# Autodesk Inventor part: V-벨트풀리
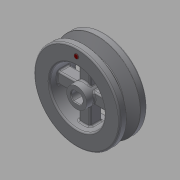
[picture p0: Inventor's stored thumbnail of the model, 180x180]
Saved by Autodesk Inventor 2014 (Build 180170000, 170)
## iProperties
Created: 2018-01
Part Number: V-벨트풀리
Material: 스테인리스강
Document SubType Name: Modeling
Designer: mduedu
Density: 8.08 g/cm^3
Appearance: 기본값
Mass: 218.724 g
Surface Area: 130.785 cm^2
Volume: 27.0698 cm^3
Author: mduedu
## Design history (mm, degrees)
sketch "스케치1"
  geometry: C1 r 30 at (0, 0); 1 further point
  constraints: 1 centre point, 1 coincident
  dimensions: "d0" = 60 diameter of C1
extrude "돌출1" new body sketch "스케치1" stored distance "d1" = 19; taper "d2" = 0 deg
sketch "스케치2"
  geometry: L1 (30, -9.5)-(-30, -9.5) reference; L2 (-30, -9.5)-(-30, 9.5) reference; L3 (-30, 9.5)-(30, 9.5) reference; L4 (30, 9.5)-(30, -9.5) reference; L5 (-30, 0)-(30, 0); L6 (30, 4.825)-(21, 2.074); L7 (21, 2.074)-(21, -2.074); L8 (21, -2.074)-(30, -4.825); L9 (30, -4.825)-(30, 4.825); L10 (27.3, 9.5)-(27.3, -9.5); L11 (0, -13.3)-(0, 13.3) reference; 4 further points
  constraints: 12 end point, 9 point on line, 3 midpoint, 2 perpendicular, 1 collinear, 1 symmetric about line
  dimensions: "d3" = 34 deg angle of L8 L6; "d4" = 2.7 distance between parallel lines of L10 L4; "d5" = 6.3 distance between parallel lines of L7 L10; "d6" = 8 distance of point (27.3, -4) point (27.3, 4)
revolve "회전1" sketch "스케치2" stored, may be unused: angle "d7" = 90 deg
fillet "모깎기1" dims "d8" = 0.2
fillet "모깎기2" dims "d9" = 0.5
fillet "모깎기3" dims "d10" = 1
sketch "스케치3"
  geometry: C1 r 19 at (0, 0); 1 further point
  constraints: 1 centre point, 1 coincident
  dimensions: "d11" = 38 diameter of C1
extrude "돌출2" cut sketch "스케치3" stored distance "d12" = 19; taper "d13" = 0 deg
sketch "스케치4"
  geometry: C1 r 7 at (0, 0); 1 further point
  constraints: 1 centre point, 1 coincident
  dimensions: "d14" = 14 diameter of C1
extrude "돌출3" join sketch "스케치4" stored distance "d15" = 19; taper "d16" = 0 deg
sketch "스케치5"
  geometry: L1 (0, 7)-(0, 19); L2 (4, 5.745)-(4, 18.574); L3 (-4, 5.745)-(-4, 18.574); C1 r 21 at (0, 0) reference; A1 r 19 centre (0, 0) between (0, 19) and (-4, 18.574) reference; A2 r 7 centre (0, 0) between (0, 7) and (-4, 5.745) reference; 1 further point
  constraints: 6 end point, 6 point on circle, 2 parallel, 1 point on line, 1 vertical, 1 other
  dimensions: "d17" = 8 distance between parallel lines of L2 L3
extrude "돌출4" join sketch "스케치5" stored distance "d18" = 8; taper "d19" = 0 deg
fillet "모깎기4" dims "d20" = 1
fillet "모깎기5" dims "d24" = 1
fillet "모깎기6" dims "d25" = 1
hole "구멍1" diameter "d28" = 8; stored, may be unused: countersink angle "d32" = 90 deg, drill point angle "d34" = 118 deg; dims "d26" = 10, "d27" = 10, "d29" = 6, "d30" = 4, "d31" = 2, "d33" = 8
sketch "스케치6"
  geometry: L1 (-2.332, -3.25)-(2.332, -3.25); L2 (2.332, 3.25)-(-2.332, 3.25); L3 (-2.332, -3.25)-(2.332, 3.25); L4 (2.332, -3.25)-(-2.332, 3.25); A1 r 4 centre (0, 0) between (2.332, 3.25) and (-2.332, 3.25) reference; A2 r 4 centre (0, 0) between (2.332, 3.25) and (-2.332, 3.25); A3 r 4 centre (0, 0) between (-2.332, -3.25) and (2.332, -3.25); 1 further point
  constraints: 8 end point, 7 point on circle, 2 centre point, 2 coincident, 2 midpoint, 1 horizontal, 1 parallel
  dimensions: "d35" = 6.5 distance of L1.end L2.start
extrude "돌출5" join sketch "스케치6" stored distance "d37" = 8; taper "d38" = 0 deg
chamfer "모따기1" distance "d39" = 0.5; stored, may be unused: second distance "d40" = 2, angle "d41" = 45 deg
chamfer "모따기2" distance "d42" = 0.5; stored, may be unused: second distance "d43" = 2, angle "d44" = 45 deg
sketch "스케치7" dims "d45" = 50
  geometry: C1 r 1.5 at (0, 25); 2 further points
  constraints: 2 vertical alignment, 1 centre point, 1 coincident, 2 other
  dimensions: "d46" = 3 diameter of C1
extrude "돌출6" join sketch "스케치7" distance "d47" = 0.5; taper "d48" = 0 deg
fillet "모깎기7" dims "d49" = 0.1
node "솔리드1"
pattern_circular "원형 패턴1" dims angle "d22" = 360 deg
node "절단 모서리 투영1"
node "절단 모서리 투영2"
